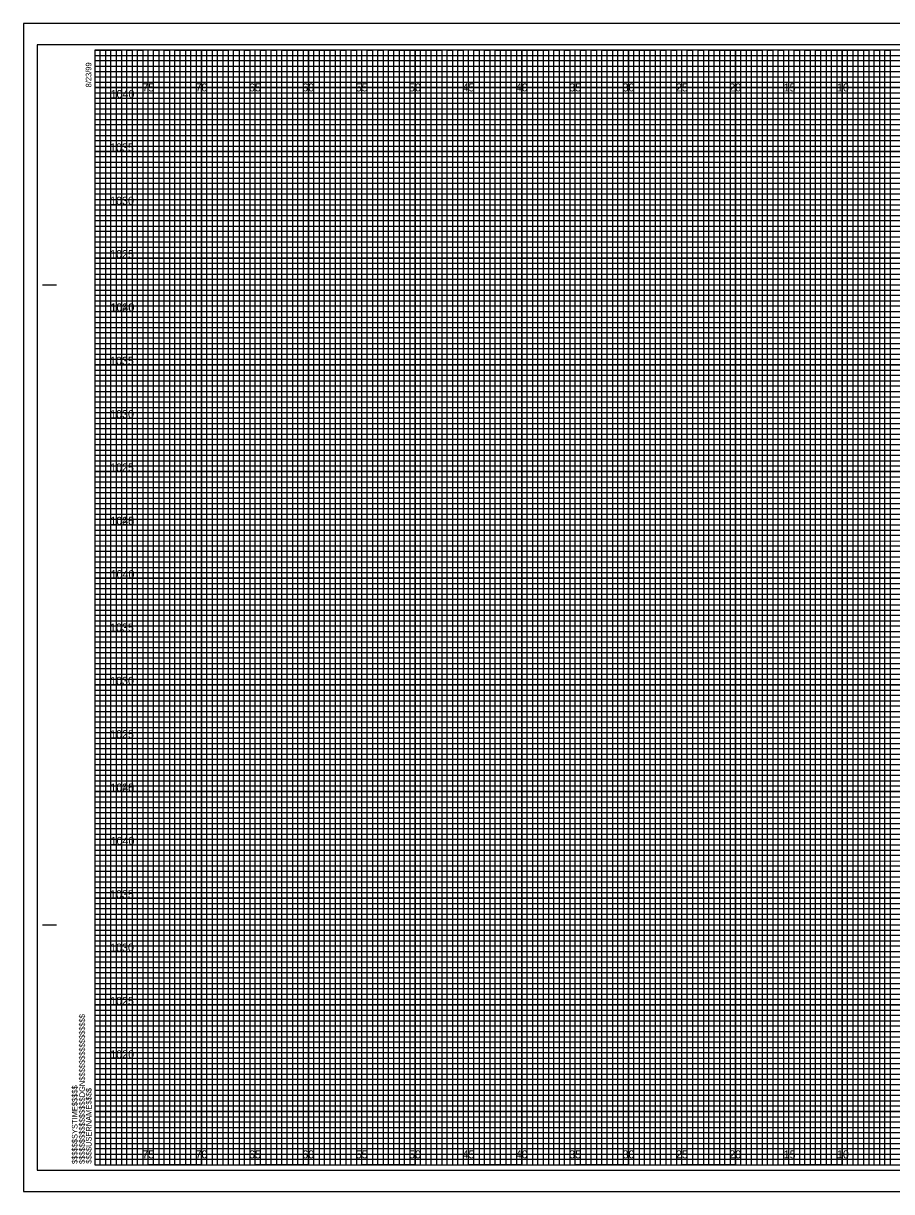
# Model space of a CAD drawing. Extents: x -7 to 162, y -2 to 987.
# Drawn here: x -6.7 to 74.6, y 767.5 to 877 of the extents above; entities that cross this region are included whole.
import ezdxf

# ---------------------------------------------------------------- set-up
doc = ezdxf.new("R2010")
doc.units = 0
for name, color, linetype in [('Exist Cross Section Cell', 7, 'Continuous'), ('Exist XS Center Line Elevation Label', 7, 'Continuous'), ('Exist XS Ground Line', 7, 'Continuous'), ('Prop CMT Concrete Structures', 7, 'Continuous'), ('Prop CMT Guardrail Widen Shoulder', 7, 'Continuous'), ('Prop CMT Pvmt Course 1', 7, 'Continuous'), ('Prop CMT Pvmt Surface', 7, 'Continuous'), ('Prop CMT Shld Paved Course 1', 7, 'Continuous'), ('Prop CMT Slope Grass', 7, 'Continuous'), ('Prop CMT Subgrade Earthwork', 7, 'Continuous'), ('Typical Text Label CELL', 7, 'Continuous')]:
    doc.layers.add(name, color=color, linetype=linetype)

msp = doc.modelspace()

# ---------------------------------------------------------------- linework, layer by layer
at = {"layer": 'Exist XS Center Line Elevation Label'}
for points in [[(0, 874.5), (2.5, 874.5), (2.5, 770), (7.5, 770), (7.5, 874.5), (12.5, 874.5), (12.5, 770), (17.5, 770), (17.5, 874.5), (22.5, 874.5), (22.5, 770), (27.5, 770), (27.5, 874.5), (32.5, 874.5), (32.5, 770), (37.5, 770), (37.5, 874.5), (42.5, 874.5), (42.5, 770), (47.5, 770), (47.5, 874.5), (52.5, 874.5), (52.5, 770), (57.5, 770), (57.5, 874.5), (62.5, 874.5), (62.5, 770), (67.5, 770), (67.5, 874.5), (72.5, 874.5), (72.5, 770), (77.5, 770)], [(0, 872), (137.5, 872)], [(0, 862.5), (160, 862.5), (160, 867.5), (0, 867.5)], [(0, 852.5), (160, 852.5), (160, 857.5), (0, 857.5)], [(0, 842.5), (160, 842.5), (160, 847.5), (0, 847.5)], [(0, 832.5), (160, 832.5), (160, 837.5), (0, 837.5)], [(0, 822.5), (160, 822.5), (160, 827.5), (0, 827.5)], [(0, 812.5), (160, 812.5), (160, 817.5), (0, 817.5)], [(0, 802.5), (160, 802.5), (160, 807.5), (0, 807.5)], [(0, 792.5), (160, 792.5), (160, 797.5), (0, 797.5)], [(0, 782.5), (160, 782.5), (160, 787.5), (0, 787.5)], [(0, 772.5), (160, 772.5), (160, 777.5), (0, 777.5)]]:
    msp.add_lwpolyline(points, dxfattribs=at)
at = {"layer": 'Exist XS Ground Line'}
for p, q in [((5, 874.5), (0, 874.5)), ((5, 770), (5, 874.5)), ((15, 874.5), (10, 874.5)), ((10, 874.5), (10, 770)), ((15, 770), (15, 874.5)), ((25, 874.5), (20, 874.5)), ((20, 874.5), (20, 770)), ((25, 770), (25, 874.5)), ((35, 874.5), (30, 874.5)), ((30, 874.5), (30, 770)), ((35, 770), (35, 874.5)), ((45, 874.5), (40, 874.5)), ((40, 874.5), (40, 770)), ((45, 770), (45, 874.5)), ((55, 874.5), (50, 874.5)), ((50, 874.5), (50, 770)), ((55, 770), (55, 874.5)), ((65, 874.5), (60, 874.5)), ((60, 874.5), (60, 770)), ((65, 770), (65, 874.5)), ((75, 874.5), (70, 874.5)), ((70, 874.5), (70, 770)), ((10, 770), (5, 770)), ((20, 770), (15, 770)), ((30, 770), (25, 770)), ((40, 770), (35, 770)), ((50, 770), (45, 770)), ((60, 770), (55, 770)), ((70, 770), (65, 770))]:
    msp.add_line(p, q, dxfattribs=at)
for points in [[(0, 870), (160, 870), (160, 865), (0, 865)], [(0, 860), (160, 860), (160, 855), (0, 855)], [(0, 850), (160, 850), (160, 845), (0, 845)], [(0, 840), (160, 840), (160, 835), (0, 835)], [(0, 830), (160, 830), (160, 825), (0, 825)], [(0, 820), (160, 820), (160, 815), (0, 815)], [(0, 810), (160, 810), (160, 805), (0, 805)], [(0, 800), (160, 800), (160, 795), (0, 795)], [(0, 790), (160, 790), (160, 785), (0, 785)], [(0, 780), (160, 780), (160, 775), (0, 775)]]:
    msp.add_lwpolyline(points, dxfattribs=at)
at = {"layer": 'Prop CMT Concrete Structures'}
for p, q in [((5, 770), (5, 874.5)), ((10, 770), (10, 874.5)), ((15, 770), (15, 874.5)), ((20, 770), (20, 874.5)), ((25, 770), (25, 874.5)), ((30, 770), (30, 874.5)), ((35, 770), (35, 874.5)), ((40, 770), (40, 874.5)), ((45, 770), (45, 874.5)), ((50, 770), (50, 874.5)), ((55, 770), (55, 874.5)), ((60, 770), (60, 874.5)), ((65, 770), (65, 874.5)), ((70, 770), (70, 874.5)), ((0, 870), (160, 870)), ((0, 865), (160, 865)), ((0, 860), (160, 860)), ((0, 855), (160, 855)), ((0, 850), (160, 850)), ((0, 845), (160, 845)), ((0, 840), (160, 840)), ((0, 835), (160, 835)), ((0, 830), (160, 830)), ((0, 825), (160, 825)), ((0, 820), (160, 820)), ((0, 815), (160, 815)), ((0, 810), (160, 810)), ((0, 805), (160, 805)), ((0, 800), (160, 800)), ((0, 795), (160, 795)), ((0, 790), (160, 790)), ((0, 785), (160, 785)), ((0, 780), (160, 780)), ((0, 775), (160, 775))]:
    msp.add_line(p, q, dxfattribs=at)
at = {"layer": 'Prop CMT Guardrail Widen Shoulder'}
for p, q in [((161.65, 877), (-6.7, 877)), ((-6.7, 877), (-6.7, 767.5)), ((-6.7, 767.5), (161.65, 767.5))]:
    msp.add_line(p, q, dxfattribs=at)
at = {"layer": 'Prop CMT Pvmt Course 1'}
msp.add_lwpolyline([(-6.7, 767.5), (161.65, 767.5), (161.65, 877), (-6.7, 877)], close=True, dxfattribs=at)
at = {"layer": 'Prop CMT Pvmt Surface'}
for points in [[(0, 770), (0.5, 770), (0.5, 874.5), (1, 874.5), (1, 770)], [(1, 770), (1.5, 770), (1.5, 874.5), (2, 874.5), (2, 770)], [(2.5, 770), (3, 770), (3, 874.5), (3.5, 874.5), (3.5, 770)], [(3.5, 770), (4, 770), (4, 874.5), (4.5, 874.5), (4.5, 770)], [(5, 770), (5.5, 770), (5.5, 874.5), (6, 874.5), (6, 770)], [(6, 770), (6.5, 770), (6.5, 874.5), (7, 874.5), (7, 770)], [(7.5, 770), (8, 770), (8, 874.5), (8.5, 874.5), (8.5, 770)], [(8.5, 770), (9, 770), (9, 874.5), (9.5, 874.5), (9.5, 770)], [(10, 770), (10.5, 770), (10.5, 874.5), (11, 874.5), (11, 770)], [(11, 770), (11.5, 770), (11.5, 874.5), (12, 874.5), (12, 770)], [(12.5, 770), (13, 770), (13, 874.5), (13.5, 874.5), (13.5, 770)], [(13.5, 770), (14, 770), (14, 874.5), (14.5, 874.5), (14.5, 770)], [(15, 770), (15.5, 770), (15.5, 874.5), (16, 874.5), (16, 770)], [(16, 770), (16.5, 770), (16.5, 874.5), (17, 874.5), (17, 770)], [(17.5, 770), (18, 770), (18, 874.5), (18.5, 874.5), (18.5, 770)], [(18.5, 770), (19, 770), (19, 874.5), (19.5, 874.5), (19.5, 770)], [(20, 770), (20.5, 770), (20.5, 874.5), (21, 874.5), (21, 770)], [(21, 770), (21.5, 770), (21.5, 874.5), (22, 874.5), (22, 770)], [(22.5, 770), (23, 770), (23, 874.5), (23.5, 874.5), (23.5, 770)], [(23.5, 770), (24, 770), (24, 874.5), (24.5, 874.5), (24.5, 770)], [(25, 770), (25.5, 770), (25.5, 874.5), (26, 874.5), (26, 770)], [(26, 770), (26.5, 770), (26.5, 874.5), (27, 874.5), (27, 770)], [(27.5, 770), (28, 770), (28, 874.5), (28.5, 874.5), (28.5, 770)], [(28.5, 770), (29, 770), (29, 874.5), (29.5, 874.5), (29.5, 770)], [(30, 770), (30.5, 770), (30.5, 874.5), (31, 874.5), (31, 770)], [(31, 770), (31.5, 770), (31.5, 874.5), (32, 874.5), (32, 770)], [(32.5, 770), (33, 770), (33, 874.5), (33.5, 874.5), (33.5, 770)], [(33.5, 770), (34, 770), (34, 874.5), (34.5, 874.5), (34.5, 770)], [(35, 770), (35.5, 770), (35.5, 874.5), (36, 874.5), (36, 770)], [(36, 770), (36.5, 770), (36.5, 874.5), (37, 874.5), (37, 770)], [(37.5, 770), (38, 770), (38, 874.5), (38.5, 874.5), (38.5, 770)], [(38.5, 770), (39, 770), (39, 874.5), (39.5, 874.5), (39.5, 770)], [(40, 770), (40.5, 770), (40.5, 874.5), (41, 874.5), (41, 770)], [(41, 770), (41.5, 770), (41.5, 874.5), (42, 874.5), (42, 770)], [(42.5, 770), (43, 770), (43, 874.5), (43.5, 874.5), (43.5, 770)], [(43.5, 770), (44, 770), (44, 874.5), (44.5, 874.5), (44.5, 770)], [(45, 770), (45.5, 770), (45.5, 874.5), (46, 874.5), (46, 770)], [(46, 770), (46.5, 770), (46.5, 874.5), (47, 874.5), (47, 770)], [(47.5, 770), (48, 770), (48, 874.5), (48.5, 874.5), (48.5, 770)], [(48.5, 770), (49, 770), (49, 874.5), (49.5, 874.5), (49.5, 770)], [(50, 770), (50.5, 770), (50.5, 874.5), (51, 874.5), (51, 770)], [(51, 770), (51.5, 770), (51.5, 874.5), (52, 874.5), (52, 770)], [(52.5, 770), (53, 770), (53, 874.5), (53.5, 874.5), (53.5, 770)], [(53.5, 770), (54, 770), (54, 874.5), (54.5, 874.5), (54.5, 770)], [(55, 770), (55.5, 770), (55.5, 874.5), (56, 874.5), (56, 770)], [(56, 770), (56.5, 770), (56.5, 874.5), (57, 874.5), (57, 770)], [(57.5, 770), (58, 770), (58, 874.5), (58.5, 874.5), (58.5, 770)], [(58.5, 770), (59, 770), (59, 874.5), (59.5, 874.5), (59.5, 770)], [(60, 770), (60.5, 770), (60.5, 874.5), (61, 874.5), (61, 770)], [(61, 770), (61.5, 770), (61.5, 874.5), (62, 874.5), (62, 770)], [(62.5, 770), (63, 770), (63, 874.5), (63.5, 874.5), (63.5, 770)], [(63.5, 770), (64, 770), (64, 874.5), (64.5, 874.5), (64.5, 770)], [(65, 770), (65.5, 770), (65.5, 874.5), (66, 874.5), (66, 770)], [(66, 770), (66.5, 770), (66.5, 874.5), (67, 874.5), (67, 770)], [(67.5, 770), (68, 770), (68, 874.5), (68.5, 874.5), (68.5, 770)], [(68.5, 770), (69, 770), (69, 874.5), (69.5, 874.5), (69.5, 770)], [(70, 770), (70.5, 770), (70.5, 874.5), (71, 874.5), (71, 770)], [(71, 770), (71.5, 770), (71.5, 874.5), (72, 874.5), (72, 770)], [(72.5, 770), (73, 770), (73, 874.5), (73.5, 874.5), (73.5, 770)], [(73.5, 770), (74, 770), (74, 874.5), (74.5, 874.5), (74.5, 770)]]:
    msp.add_lwpolyline(points, dxfattribs=at)
at = {"layer": 'Prop CMT Shld Paved Course 1'}
for p, q in [((0, 874), (130, 874)), ((130, 873.49), (0, 873.49)), ((0, 873.49), (0, 873)), ((0, 873), (130, 873)), ((130, 872.45), (0, 872.45)), ((0, 872.45), (0, 871.5)), ((0, 871.5), (160, 871.5))]:
    msp.add_line(p, q, dxfattribs=at)
for points in [[(0, 871), (135, 871), (160, 871), (160, 871), (0, 871)], [(0, 870.5), (160, 870.5), (160, 869.5), (0, 869.5)], [(0, 869), (160, 869), (160, 868.5), (0, 868.49)], [(0, 868), (160, 868), (160, 867), (0, 867)], [(0, 866.5), (160, 866.5), (160, 866), (0, 866)], [(0, 865.5), (160, 865.5), (160, 864.5), (0, 864.5)], [(0, 864), (160, 864), (160, 863.5), (0, 863.5)], [(0, 863), (160, 863), (160, 862), (0, 862)], [(0, 861.5), (160, 861.5), (160, 861), (0, 861)], [(0, 860.5), (160, 860.5), (160, 859.5), (0, 859.5)], [(0, 859), (160, 859), (160, 858.5), (0, 858.5)], [(0, 858), (160, 858), (160, 856.98), (160, 856.5), (160, 856), (0, 856)], [(0, 857), (160, 857), (160, 856.5), (0, 856.5)], [(0, 855.5), (160, 855.5), (160, 854.5), (0, 854.51)], [(0, 854.51), (160, 854.5), (160, 854), (0, 854)], [(0, 853.5), (160, 853.5), (160, 853), (0, 853)], [(0, 852), (160, 852), (160, 851.5), (0, 851.5)], [(0, 851), (160, 851), (160, 850.5), (0, 850.5)], [(-0.04, 849.45), (160, 849.45), (160, 848.94), (-0.04, 848.94)], [(0, 848.5), (160, 848.5), (160, 848), (0, 848)], [(0, 847), (160, 847), (160, 846.5), (0, 846.5)], [(0, 846), (160, 846), (160, 845.5), (0, 845.5)], [(0, 844.5), (160, 844.5), (160, 844), (0, 844)], [(0, 843.5), (160, 843.5), (160, 843), (0, 843)], [(0, 842), (160, 842), (160, 841.5), (0, 841.5)], [(0, 841), (160, 841), (160, 840.5), (0, 840.5)], [(0, 839.5), (160, 839.5), (160, 838.99), (0, 839)], [(0, 838.5), (160, 838.5), (160, 838), (0, 838)], [(0, 837), (160, 837), (160, 836.5), (0, 836.5)], [(0, 836), (160, 836), (160, 835.5), (0, 835.5)], [(0, 834.5), (160, 834.5), (160, 834), (0, 834)], [(0, 833.5), (160, 833.5), (160, 833), (0, 833)], [(0, 832), (160, 832), (160, 831.5), (0, 831.5)], [(0, 831), (160, 831), (160, 830.5), (0, 830.5)], [(0, 829.5), (160, 829.5), (160, 829), (0, 829)], [(0, 828.5), (160.03, 828.46), (160, 828), (0, 828)], [(0, 827), (160, 827), (160, 826.5), (0, 826.5)], [(0, 826), (160, 826), (160, 825.5), (0, 825.5)], [(0, 824.5), (160, 824.5), (160, 824), (0, 824)], [(0, 823.5), (160, 823.5), (160, 823), (0, 823)], [(0, 822), (160, 822), (160, 821.5), (0, 821.5)], [(0, 821), (160, 821), (160, 820.5), (0, 820.5)], [(0, 819.5), (160, 819.5), (160, 819), (0, 819)], [(0, 818.5), (160, 818.5), (160, 818), (0, 818)], [(0, 817), (160, 817), (160, 816.5), (0, 816.5)], [(0, 816), (160, 816), (160, 815.5), (0, 815.5)], [(0, 814.5), (160, 814.5), (160, 814), (0, 814)], [(0, 813.5), (160, 813.5), (160, 813), (0, 813)], [(0, 812), (160, 812), (160, 811.5), (0, 811.5)], [(0, 811), (160, 811), (160, 810.5), (0, 810.5)], [(0, 809.5), (160, 809.5), (160, 808.99), (0, 809)], [(0, 808.5), (160, 808.5), (160, 808), (0, 808)], [(0, 807), (160, 807), (160, 806.5), (0, 806.5)], [(0, 806), (160, 806), (160, 805.5), (0, 805.5)], [(0, 804.5), (160, 804.5), (160, 804), (0, 804)], [(0, 803.5), (160, 803.5), (160, 803), (0, 803)], [(0, 802), (160, 802), (160, 801.5), (0, 801.5)], [(0, 801), (160, 801), (160, 800.5), (0, 800.5)], [(0, 799.5), (160, 799.5), (160, 799), (0, 799)], [(0, 798.5), (160.03, 798.46), (160, 798), (0, 798)], [(0, 797), (160, 797), (160, 796.5), (0, 796.5)], [(0, 796), (160, 796), (160, 795.5), (0, 795.5)], [(0, 794.5), (160, 794.5), (160, 794), (0, 794)], [(0, 793.5), (160, 793.5), (160, 793), (0, 793)], [(0, 792), (160, 792), (160, 791.5), (0, 791.5)], [(0, 791), (160, 791), (160, 790.5), (0, 790.5)], [(0, 789.5), (160, 789.5), (160, 789), (0, 789)], [(0, 788.5), (160, 788.5), (160, 788), (0, 788)], [(0, 787), (160, 787), (160, 786.5), (0, 786.5)], [(0, 786), (160, 786), (160, 785.5), (0, 785.5)], [(0, 784.5), (160, 784.5), (160, 784), (0, 784)], [(0, 783.5), (160, 783.5), (160, 783), (0, 783)], [(0, 782), (160, 782), (160, 781.5), (0, 781.5)], [(0, 781), (160, 781), (160, 780.5), (0, 780.5)], [(0, 779.5), (160, 779.5), (160, 779), (0, 779)], [(0, 778.5), (160, 778.5), (160, 778), (0, 778)], [(0, 777), (160, 777), (160, 776.5), (0, 776.5)], [(0, 776), (160, 776), (160, 775.5), (0, 775.5)], [(0, 774.5), (160, 774.5), (160, 774), (0, 774)], [(0, 773.5), (160, 773.5), (160, 773), (0, 773)], [(0, 772), (160, 772), (160, 771.5), (0, 771.5)], [(0, 771), (160, 771), (160, 770.5), (0, 770.5)]]:
    msp.add_lwpolyline(points, dxfattribs=at)
at = {"layer": 'Prop CMT Slope Grass'}
msp.add_lwpolyline([(-5.4, 769.5), (161.2, 769.5), (161.2, 875), (-5.4, 875)], close=True, dxfattribs=at)
at = {"layer": 'Prop CMT Subgrade Earthwork'}
for p, q in [((-4.9, 852.5), (-3.65, 852.5)), ((-4.85, 852.5), (-3.6, 852.5)), ((-4.9, 792.5), (-3.65, 792.5)), ((-4.85, 792.5), (-3.6, 792.5)), ((0, 770), (0, 770)), ((0, 770), (0, 770)), ((0, 770), (0, 770)), ((0, 770), (0, 770)), ((0, 770), (0, 770)), ((0, 770), (0, 770)), ((0, 770), (0, 770))]:
    msp.add_line(p, q, dxfattribs=at)
msp.add_lwpolyline([(160, 874.5), (0, 874.5), (0, 770), (160, 770)], close=True, dxfattribs=at)

# ---------------------------------------------------------------- texts
at = {"layer": 'Exist Cross Section Cell'}
for s, p in [('75', (4.44, 870.62)), ('70', (9.43, 870.62)), ('65', (14.44, 870.62)), ('60', (19.43, 870.62)), ('55', (24.44, 870.62)), ('50', (29.43, 870.62)), ('45', (34.44, 870.62)), ('40', (39.43, 870.62)), ('35', (44.44, 870.62)), ('30', (49.43, 870.62)), ('25', (54.44, 870.62)), ('20', (59.43, 870.62)), ('15', (64.53, 870.62)), ('10', (69.52, 870.62)), ('75', (4.44, 770.62)), ('70', (9.43, 770.62)), ('65', (14.44, 770.62)), ('60', (19.43, 770.62)), ('55', (24.44, 770.62)), ('50', (29.43, 770.62)), ('45', (34.44, 770.62)), ('40', (39.43, 770.62)), ('35', (44.44, 770.62)), ('30', (49.43, 770.62)), ('25', (54.44, 770.62)), ('20', (59.43, 770.62)), ('15', (64.53, 770.62)), ('10', (69.52, 770.62))]:
    msp.add_text(s, height=0.75, dxfattribs=at).set_placement(p)
at = {"layer": 'Prop CMT Subgrade Earthwork'}
for s, p in [('8/23/99', (-0.33, 871)), ('$$$$$$$$$$$$$$$$DGN$$$$$$$$$$$$$$$$', (-0.94, 770.09)), ('$$$$$$SYSTIME$$$$$', (-1.63, 770.09)), ('$$$$USERNAME$$$$', (-0.31, 770.12))]:
    msp.add_text(s, height=0.525, rotation=90, dxfattribs=at).set_placement(p)
at = {"layer": 'Typical Text Label CELL'}
for s, p in [('1040', (1.47, 870)), ('1035', (1.42, 865)), ('1030', (1.43, 860)), ('1025', (1.43, 855)), ('1020', (1.44, 850)), ('1040', (1.47, 850)), ('1035', (1.42, 845)), ('1030', (1.43, 840)), ('1025', (1.43, 835)), ('1020', (1.44, 830)), ('1045', (1.46, 830)), ('1040', (1.47, 825)), ('1035', (1.42, 820)), ('1030', (1.43, 815)), ('1025', (1.43, 810)), ('1020', (1.44, 805)), ('1045', (1.46, 805)), ('1040', (1.47, 800)), ('1035', (1.42, 795)), ('1030', (1.43, 790)), ('1025', (1.43, 785)), ('1020', (1.44, 780))]:
    msp.add_text(s, height=0.75, dxfattribs=at).set_placement(p)

doc.saveas('drawing.dxf')
